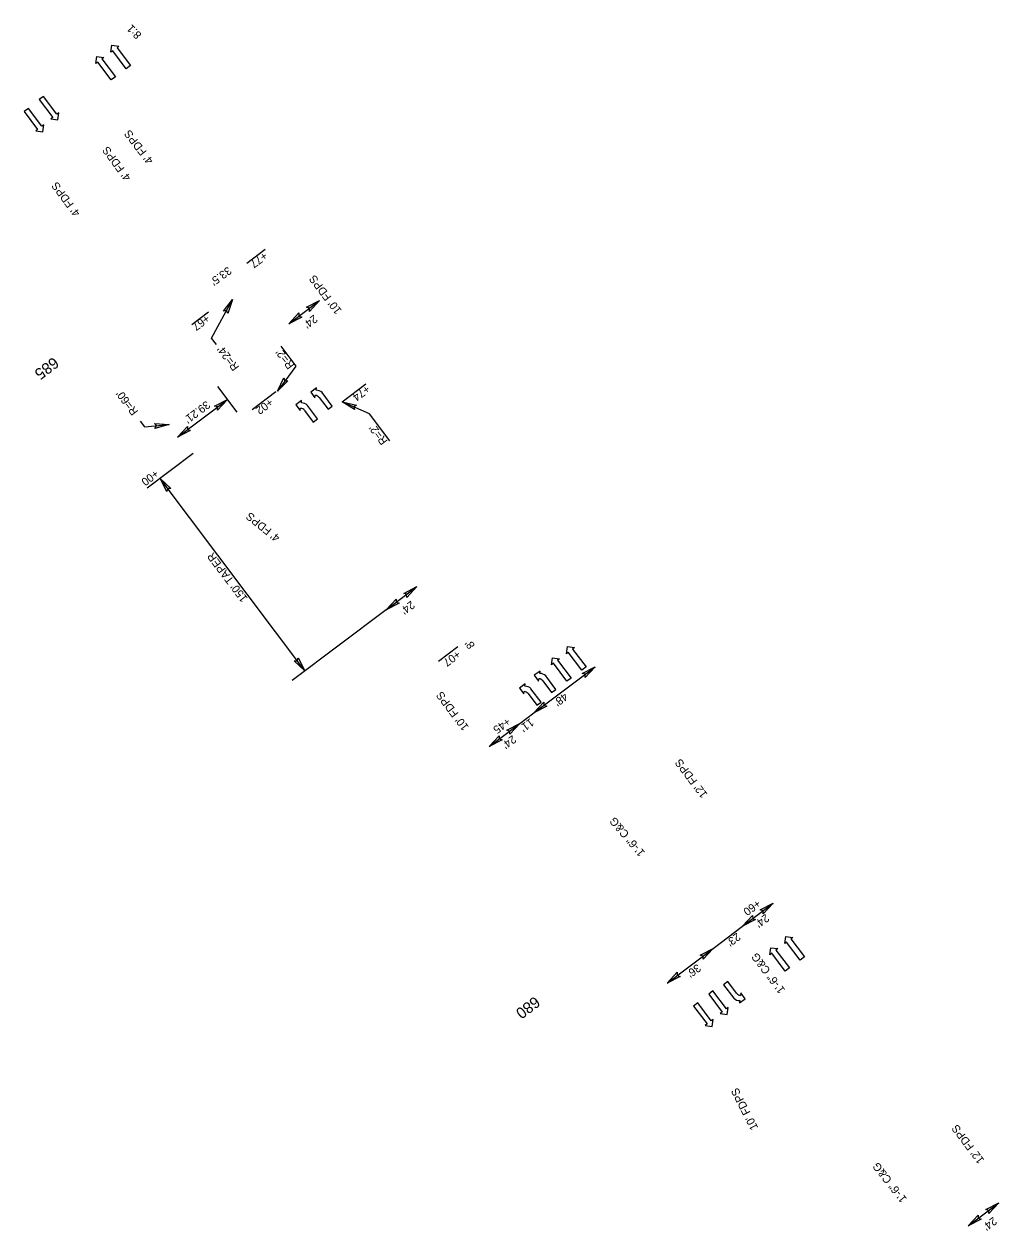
# Model space of a CAD drawing. Extents: x 1262692 to 1264138, y 775643 to 777474.
# Drawn here: x 1262692 to 1263301, y 776720 to 777474 of the extents above; entities that cross this region are included whole.
import ezdxf

# ---------------------------------------------------------------- set-up
doc = ezdxf.new("R2010")
doc.units = 0
for name, color, linetype in [('Prop Dimension', 7, 'Continuous'), ('Prop Dimension Text', 7, 'Continuous'), ('Prop Horizontal Alignment Tick Label', 7, 'Continuous'), ('Prop Lane Arrow CELL', 7, 'Continuous'), ('Prop Lane Lines', 7, 'Continuous'), ('Prop Terminator CELL', 7, 'Continuous')]:
    doc.layers.add(name, color=color, linetype=linetype)

msp = doc.modelspace()

# ---------------------------------------------------------------- linework, layer by layer
at = {"layer": 'Prop Dimension'}
for p, q in [((1262831.31, 777324.62), (1262842.72, 777333.22)), ((1262857.57, 777286.69), (1262876.74, 777301.13)), ((1262797.05, 777286.3), (1262807.34, 777294.05)), ((1262890.85, 777237.92), (1262905.71, 777249.11)), ((1262787.9, 777215.83), (1262819.22, 777239.42)), ((1262834.7, 777233.12), (1262849.56, 777244.32)), ((1262797.85, 777205.59), (1262769.09, 777183.93)), ((1262867.6, 777069.77), (1262777.08, 777189.95)), ((1262918.32, 777107.97), (1262937.49, 777122.41)), ((1262918.32, 777107.97), (1262859.61, 777063.75)), ((1262951.22, 777075.94), (1262963.15, 777084.92)), ((1263010.68, 777043.51), (1263049.02, 777072.39)), ((1263001.9, 777036.9), (1263010.68, 777043.51)), ((1262982.73, 777022.46), (1263001.9, 777036.9)), ((1263141.16, 776910.18), (1263160.33, 776924.62)), ((1263122.79, 776896.34), (1263141.16, 776910.18)), ((1263094.03, 776874.68), (1263122.79, 776896.34)), ((1263282.16, 776722.98), (1263301.33, 776737.42))]:
    msp.add_line(p, q, dxfattribs=at)
at = {"layer": 'Prop Dimension Text'}
for p, q in [((1262809.28, 777277.63), (1262822.39, 777301.8)), ((1262812.29, 777273.63), (1262809.28, 777277.63)), ((1262852.65, 777272.68), (1262862.03, 777260.22)), ((1262862.03, 777260.22), (1262850.42, 777244.65)), ((1262908.05, 777230.41), (1262890.85, 777237.92)), ((1262764.77, 777225.85), (1262767.47, 777222.26)), ((1262767.47, 777222.26), (1262782.76, 777223.81)), ((1262920.72, 777213.59), (1262908.05, 777230.41))]:
    msp.add_line(p, q, dxfattribs=at)
at = {"layer": 'Prop Lane Arrow CELL'}
for p, q in [((1262746.4, 777456.29), (1262746.98, 777460.67)), ((1262746.98, 777460.67), (1262751.43, 777460.08)), ((1262751.43, 777460.08), (1262750.23, 777459.18)), ((1262750.23, 777459.18), (1262758.66, 777447.99)), ((1262736.96, 777449.28), (1262737.54, 777453.66)), ((1262738.16, 777450.18), (1262736.96, 777449.28)), ((1262737.54, 777453.66), (1262741.99, 777453.07)), ((1262746.58, 777439), (1262738.16, 777450.18)), ((1262741.99, 777453.07), (1262740.79, 777452.17)), ((1262740.79, 777452.17), (1262749.22, 777440.98)), ((1262747.6, 777457.19), (1262746.4, 777456.29)), ((1262756.02, 777446.01), (1262747.6, 777457.19)), ((1262758.66, 777447.99), (1262756.02, 777446.01)), ((1262749.22, 777440.98), (1262746.58, 777439)), ((1262704.24, 777428.76), (1262701.61, 777426.78)), ((1262712.67, 777417.58), (1262704.24, 777428.76)), ((1262694.79, 777421.29), (1262692.15, 777419.31)), ((1262703.21, 777410.11), (1262694.79, 777421.29)), ((1262701.61, 777426.78), (1262710.03, 777415.59)), ((1262692.15, 777419.31), (1262700.57, 777408.12)), ((1262710.03, 777415.59), (1262708.83, 777414.69)), ((1262708.83, 777414.69), (1262713.21, 777414.04)), ((1262713.87, 777418.48), (1262712.67, 777417.58)), ((1262713.21, 777414.04), (1262713.87, 777418.48)), ((1262700.57, 777408.12), (1262699.37, 777407.22)), ((1262699.37, 777407.22), (1262703.75, 777406.57)), ((1262704.41, 777411.01), (1262703.21, 777410.11)), ((1262703.75, 777406.57), (1262704.41, 777411.01)), ((1262874.8, 777246.62), (1262871.26, 777244.02)), ((1262874.59, 777245.15), (1262874.8, 777246.62)), ((1262871.26, 777244.02), (1262873.92, 777240.39)), ((1262873.92, 777240.39), (1262874.13, 777241.86)), ((1262876.55, 777240.56), (1262882.06, 777233.25)), ((1262884.69, 777235.23), (1262878.35, 777243.66)), ((1262865.6, 777238.64), (1262862.06, 777236.03)), ((1262862.06, 777236.03), (1262864.73, 777232.41)), ((1262864.73, 777232.41), (1262864.93, 777233.88)), ((1262865.4, 777237.17), (1262865.6, 777238.64)), ((1262867.36, 777232.58), (1262872.86, 777225.27)), ((1262875.5, 777227.25), (1262869.15, 777235.68)), ((1262882.06, 777233.25), (1262884.69, 777235.23)), ((1262872.86, 777225.27), (1262875.5, 777227.25)), ((1263031.06, 777080.53), (1263031.64, 777084.91)), ((1263032.26, 777081.44), (1263031.06, 777080.53)), ((1263031.64, 777084.91), (1263036.09, 777084.32)), ((1263040.68, 777070.25), (1263032.26, 777081.44)), ((1263036.09, 777084.32), (1263034.9, 777083.42)), ((1263034.9, 777083.42), (1263043.32, 777072.24)), ((1263021.71, 777073.59), (1263022.3, 777077.98)), ((1263022.91, 777074.5), (1263021.71, 777073.59)), ((1263022.3, 777077.98), (1263026.75, 777077.38)), ((1263031.34, 777063.31), (1263022.91, 777074.5)), ((1263026.75, 777077.38), (1263025.55, 777076.48)), ((1263025.55, 777076.48), (1263033.97, 777065.3)), ((1263014.56, 777069.6), (1263011.01, 777067)), ((1263011.01, 777067), (1263013.68, 777063.37)), ((1263014.35, 777068.13), (1263014.56, 777069.6)), ((1263024.45, 777058.21), (1263018.1, 777066.64)), ((1263033.97, 777065.3), (1263031.34, 777063.31)), ((1263043.32, 777072.24), (1263040.68, 777070.25)), ((1263005.36, 777061.62), (1263001.82, 777059.02)), ((1263001.82, 777059.02), (1263004.48, 777055.39)), ((1263005.15, 777060.15), (1263005.36, 777061.62)), ((1263015.25, 777050.23), (1263008.91, 777058.66)), ((1263013.68, 777063.37), (1263013.89, 777064.84)), ((1263016.31, 777063.54), (1263021.81, 777056.23)), ((1263021.81, 777056.23), (1263024.45, 777058.21)), ((1263004.48, 777055.39), (1263004.69, 777056.86)), ((1263007.11, 777055.56), (1263012.62, 777048.25)), ((1263012.62, 777048.25), (1263015.25, 777050.23)), ((1263167.51, 776899.37), (1263168.1, 776903.75)), ((1263168.71, 776900.27), (1263167.51, 776899.37)), ((1263168.1, 776903.75), (1263172.55, 776903.16)), ((1263177.14, 776889.09), (1263168.71, 776900.27)), ((1263172.55, 776903.16), (1263171.35, 776902.26)), ((1263171.35, 776902.26), (1263179.77, 776891.08)), ((1263158.17, 776892.43), (1263158.75, 776896.81)), ((1263159.37, 776893.33), (1263158.17, 776892.43)), ((1263158.75, 776896.81), (1263163.2, 776896.22)), ((1263167.79, 776882.15), (1263159.37, 776893.33)), ((1263163.2, 776896.22), (1263162, 776895.32)), ((1263162, 776895.32), (1263170.42, 776884.14)), ((1263179.77, 776891.08), (1263177.14, 776889.09)), ((1263170.42, 776884.14), (1263167.79, 776882.15)), ((1263122.63, 776869.77), (1263119.99, 776867.79)), ((1263131.05, 776858.59), (1263122.63, 776869.77)), ((1263131.96, 776875.64), (1263129.32, 776873.65)), ((1263129.32, 776873.65), (1263135.67, 776865.23)), ((1263137.46, 776868.33), (1263131.96, 776875.64)), ((1263113.17, 776862.3), (1263110.53, 776860.31)), ((1263121.59, 776851.12), (1263113.17, 776862.3)), ((1263119.99, 776867.79), (1263128.41, 776856.6)), ((1263139.21, 776862.26), (1263142.76, 776864.87)), ((1263139.42, 776863.73), (1263139.21, 776862.26)), ((1263140.09, 776868.5), (1263139.88, 776867.03)), ((1263142.76, 776864.87), (1263140.09, 776868.5)), ((1263110.53, 776860.31), (1263118.95, 776849.13)), ((1263128.41, 776856.6), (1263127.21, 776855.7)), ((1263127.21, 776855.7), (1263131.59, 776855.05)), ((1263132.25, 776859.49), (1263131.05, 776858.59)), ((1263131.59, 776855.05), (1263132.25, 776859.49)), ((1263118.95, 776849.13), (1263117.75, 776848.23)), ((1263117.75, 776848.23), (1263122.13, 776847.58)), ((1263122.79, 776852.02), (1263121.59, 776851.12)), ((1263122.13, 776847.58), (1263122.79, 776852.02))]:
    msp.add_line(p, q, dxfattribs=at)
for centre, radius, start, end in [((1262873.94, 777238.61), 3.27, 36.98742, 86.64559), ((1262874.69, 777239.91), 5.25, 45.66349, 90.97518), ((1262864.75, 777230.62), 3.27, 36.98742, 86.64559), ((1262865.49, 777231.93), 5.25, 45.66349, 90.97518), ((1263014.45, 777062.9), 5.25, 45.66349, 90.97518), ((1263005.25, 777054.91), 5.25, 45.66349, 90.97518), ((1263013.7, 777061.59), 3.27, 36.98742, 86.64559), ((1263004.51, 777053.6), 3.27, 36.98742, 86.64559), ((1263139.32, 776868.97), 5.25, 225.66349, 270.97518), ((1263140.07, 776870.28), 3.27, 216.98742, 266.64559)]:
    msp.add_arc(centre, radius, start, end, dxfattribs=at)
at = {"layer": 'Prop Lane Lines'}
msp.add_line((1262825.24, 777231.43), (1262813.2, 777247.41), dxfattribs=at)
at = {"layer": 'Prop Terminator CELL'}
for points in [[(1262816.74, 777294.63), (1262822.39, 777301.8), (1262819.48, 777293.09), (1262818.63, 777294.86)], [(1262868.62, 777296.95), (1262876.74, 777301.13), (1262870.48, 777294.41), (1262870.43, 777296.38)], [(1262865.69, 777290.87), (1262857.57, 777286.69), (1262863.84, 777293.41), (1262863.88, 777291.44)], [(1262857.05, 777250.93), (1262850.42, 777244.65), (1262854.56, 777252.86), (1262855.15, 777250.98)], [(1262811.1, 777235.24), (1262819.22, 777239.42), (1262812.95, 777232.7), (1262812.91, 777234.67)], [(1262898.55, 777233.01), (1262890.85, 777237.92), (1262899.81, 777235.89), (1262898.13, 777234.86)], [(1262773.65, 777224.45), (1262782.76, 777223.81), (1262773.92, 777221.31), (1262774.9, 777223.02)], [(1262796.02, 777220.01), (1262787.9, 777215.83), (1262794.17, 777222.56), (1262794.21, 777220.59)], [(1262781.25, 777181.83), (1262777.08, 777189.95), (1262783.8, 777183.68), (1262781.83, 777183.64)], [(1262929.37, 777118.23), (1262937.49, 777122.41), (1262931.23, 777115.69), (1262931.18, 777117.66)], [(1262926.44, 777112.15), (1262918.32, 777107.97), (1262924.59, 777114.69), (1262924.63, 777112.72)], [(1262863.42, 777077.89), (1262867.6, 777069.77), (1262860.88, 777076.03), (1262862.85, 777076.08)], [(1263040.9, 777068.21), (1263049.02, 777072.39), (1263042.75, 777065.66), (1263042.71, 777067.63)], [(1263018.8, 777047.69), (1263010.68, 777043.51), (1263016.95, 777050.23), (1263016.99, 777048.26)], [(1262993.78, 777032.72), (1263001.9, 777036.9), (1262995.63, 777030.17), (1262995.59, 777032.14)], [(1262990.85, 777026.63), (1262982.73, 777022.46), (1262989, 777029.18), (1262989.04, 777027.21)], [(1263152.21, 776920.45), (1263160.33, 776924.62), (1263154.07, 776917.9), (1263154.02, 776919.87)], [(1263149.28, 776914.36), (1263141.16, 776910.18), (1263147.43, 776916.91), (1263147.47, 776914.94)], [(1263114.66, 776892.16), (1263122.79, 776896.34), (1263116.52, 776889.62), (1263116.48, 776891.59)], [(1263102.16, 776878.86), (1263094.03, 776874.68), (1263100.3, 776881.41), (1263100.34, 776879.44)], [(1263293.21, 776733.24), (1263301.33, 776737.42), (1263295.07, 776730.7), (1263295.02, 776732.67)], [(1263290.28, 776727.16), (1263282.16, 776722.98), (1263288.43, 776729.7), (1263288.47, 776727.73)]]:
    msp.add_lwpolyline(points, close=True, dxfattribs=at)

# ---------------------------------------------------------------- texts
at = {"layer": 'Prop Dimension'}
for s, p in [("R=24'", (1262826.83, 777259.63)), ("R=2'", (1262861.2, 777260.68)), ("R=60'", (1262763.68, 777231.79)), ("R=2'", (1262919.53, 777213.36)), ("8'", (1262974.19, 777085.78))]:
    msp.add_text(s, height=5, rotation=126.98742, dxfattribs=at).set_placement(p)
at = {"layer": 'Prop Dimension Text'}
for s, rotation, p in [('8:1', 134.64078, (1262765.89, 777467.52)), ("4' FDPS", 127.54773, (1262773.24, 777388.76)), ("4' FDPS", 126.32925, (1262759.24, 777378.15)), ("4' FDPS", 126.32925, (1262727.5, 777355.92)), ('+77', 216.15024, (1262842, 777331.89)), ("33.5'", 216.15024, (1262819.49, 777322.67)), ("10' FDPS", 126.98742, (1262890.88, 777294.96)), ("24'", 216.15024, (1262873.26, 777292.55)), ('+67', 216.15024, (1262805.94, 777292.71)), ('+74', 216.15024, (1262906.08, 777248.63)), ('+02', 216.15024, (1262845.53, 777240.35)), ("39.21'", 216.98742, (1262806.03, 777238.85)), ('+00', 216.98742, (1262773.94, 777195.79)), ("4' FDPS", 140.98263, (1262852.53, 777153.73)), ("150' TAPER", 126.98742, (1262832.11, 777115.02)), ("24'", 216.15024, (1262934.01, 777113.83)), ('+07', 216.15024, (1262962.68, 777082.86)), ("10' FDPS", 126.98742, (1262970.32, 777034.71)), ("48'", 216.15024, (1263029.77, 777056.45)), ('+45', 216.15024, (1262993.88, 777040.84)), ("11'", 216.15024, (1263008.5, 777040.41)), ("24'", 216.15024, (1262997.38, 777029.83)), ("12' FDPS", 126.98742, (1263119.55, 776992.61)), ('1\'-6" C&G', 130.21917, (1263080.44, 776956.32)), ('+60', 216.15024, (1263150.25, 776927.13)), ("24'", 216.15024, (1263155.55, 776918.15)), ("23'", 216.15024, (1263137.64, 776906.42)), ('1\'-6" C&G', 126.98742, (1263167.98, 776870.47)), ("36'", 216.15024, (1263112.82, 776886.94)), ("10' FDPS", 116.89444, (1263150.99, 776784.33)), ("12' FDPS", 126.98742, (1263292.48, 776764.1)), ('1\'-6" C&G', 128.0506, (1263244.11, 776739.87)), ("24'", 216.15024, (1263297.86, 776728.84))]:
    msp.add_text(s, height=5, rotation=rotation, dxfattribs=at).set_placement(p)
at = {"layer": 'Prop Horizontal Alignment Tick Label'}
for s, p in [('685', (1262710.49, 777266.24)), ('680', (1263011.24, 776866.8))]:
    msp.add_text(s, height=7, rotation=216.98742, dxfattribs=at).set_placement(p)

doc.saveas('drawing.dxf')
